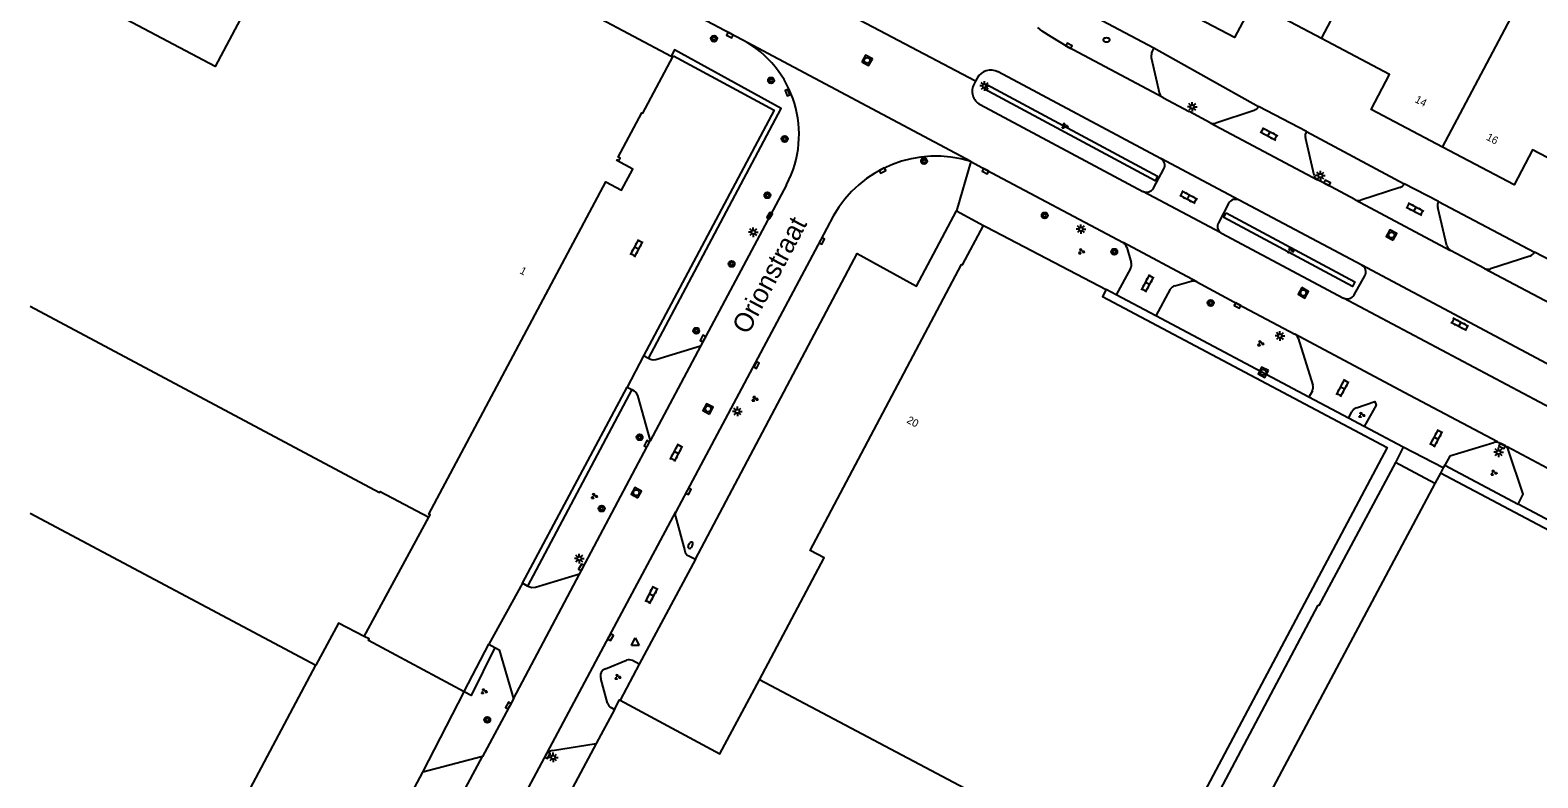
# Model space of a CAD drawing. Extents: x 135999 to 138000, y 396000 to 398501.
# Drawn here: x 136000 to 136196.7, y 398288.4 to 398385.9 of the extents above; entities that cross this region are included whole.
import ezdxf

# ---------------------------------------------------------------- set-up
doc = ezdxf.new("R2010")
doc.units = 0
for name, color, linetype in [('gg-afsc-hekwerk', 7, 'Continuous'), ('gg-anno-huisnummerreeks BGT', 7, 'Continuous'), ('gg-anno-openbare ruimte label', 7, 'Continuous'), ('gg-bbg-bijgebouw', 7, 'Continuous'), ('gg-bbg-hoofdgebouw', 7, 'Continuous'), ('gg-bbg-tussenscheiding', 7, 'Continuous'), ('gg-knt-verharding', 7, 'Continuous'), ('gg-knt-verharding nz', 7, 'Continuous'), ('gt-grn-groengrens', 7, 'Continuous'), ('gt-grn-vlakafsluiter', 7, 'Continuous'), ('gt-grn-weggrens', 7, 'Continuous'), ('gt-symb-boom', 7, 'Continuous'), ('gt-symb-brandkraan', 7, 'Continuous'), ('gt-symb-groenvak', 7, 'Continuous'), ('gt-symb-klinker verharding', 7, 'Continuous'), ('gt-symb-kolk', 7, 'Continuous'), ('gt-symb-lichtmast', 7, 'Continuous'), ('gt-symb-rioolschacht', 7, 'Continuous'), ('gt-symb-waterafsluiter', 7, 'Continuous')]:
    doc.layers.add(name, color=color, linetype=linetype)

# ---------------------------------------------------------------- blocks, each defined once
blk = doc.blocks.new('gt0-RS')
at = {"layer": 'gt-symb-rioolschacht'}
blk.add_lwpolyline([(-0.5, -0.5), (0.5, -0.5), (0.5, 0.5), (-0.5, 0.5)], close=True, dxfattribs=at)
blk.add_circle((0, 0), 0.375, dxfattribs=at)
blk = doc.blocks.new('gt0-BOOM')
at = {"layer": 'gt-symb-boom'}
for radius in [0.4, 0.2]:
    blk.add_circle((0, 0), radius, dxfattribs=at)
blk = doc.blocks.new('gt0-KOLK')
at = {"layer": 'gt-symb-kolk'}
blk.add_lwpolyline([(0, 0), (0.38, 0), (0.38, 0.4), (-0.38, 0.4), (-0.38, 0), (0, 0)], dxfattribs=at)
blk = doc.blocks.new('gt0-KL1')
at = {"layer": 'gt-symb-klinker verharding'}
for p, q in [((-1.15, 0.3), (1.15, 0.3)), ((-1, -0.3), (-1, 0.3)), ((-0.5, 0.3), (-0.5, 0.45)), ((0, -0.3), (0, 0.3)), ((0.5, 0.3), (0.5, 0.45)), ((1, -0.3), (1, 0.3)), ((-1.15, -0.3), (1.15, -0.3)), ((-0.5, -0.45), (-0.5, -0.3)), ((0.5, -0.45), (0.5, -0.3))]:
    blk.add_line(p, q, dxfattribs=at)
blk = doc.blocks.new('gt0-LMAST')
at = {"layer": 'gt-symb-lichtmast'}
for p, q in [((-0.18, 0.17), (-0.45, 0.44)), ((-0.01, 0.25), (-0.01, 0.62)), ((0.17, 0.17), (0.44, 0.44)), ((-0.26, 0), (-0.63, 0)), ((-0.18, -0.18), (-0.45, -0.45)), ((-0.01, -0.25), (-0.01, -0.63)), ((0.44, -0.45), (0.17, -0.18)), ((0.24, 0), (0.62, 0))]:
    blk.add_line(p, q, dxfattribs=at)
blk.add_circle((-0.01, 0), 0.25, dxfattribs=at)
blk = doc.blocks.new('gt0-BR')
at = {"layer": 'gt-symb-brandkraan'}
for centre, radius, start, end in [((-0.24, 0), 0.206, 107.5669, 252.4331), ((0.6, -2.66), 3, 106.892, 107.5669), ((0, -0.69), 0.938, 73.108, 106.892), ((-0.6, -2.66), 3, 72.4331, 73.108), ((0.24, 0), 0.206, 287.567, 72.4331), ((0.6, 2.66), 3, 252.4331, 253.108), ((0, 0.69), 0.938, 253.108, 286.8921), ((-0.6, 2.66), 3, 286.8921, 287.567)]:
    blk.add_arc(centre, radius, start, end, dxfattribs=at)
blk = doc.blocks.new('gt0-GRVAK')
at = {"layer": 'gt-symb-groenvak'}
for p, q in [((-0.11, 0.19), (-0.23, 0.24)), ((-0.18, 0.15), (0.09, 0.15)), ((-0.09, 0.21), (-0.16, 0.32)), ((-0.05, 0.21), (-0.05, 0.39)), ((0, 0.21), (0.06, 0.32)), ((0.02, 0.19), (0.13, 0.24)), ((0.26, -0.05), (0.2, 0.06)), ((0.3, -0.05), (0.3, 0.13)), ((0.35, -0.05), (0.41, 0.06)), ((-0.24, -0.23), (-0.36, -0.18)), ((-0.32, -0.26), (-0.05, -0.26)), ((-0.23, -0.21), (-0.29, -0.1)), ((-0.18, -0.2), (-0.18, -0.02)), ((-0.14, -0.21), (-0.07, -0.1)), ((-0.12, -0.23), (0, -0.18)), ((0.24, -0.07), (0.12, -0.02)), ((0.17, -0.11), (0.44, -0.11)), ((0.37, -0.07), (0.49, -0.02))]:
    blk.add_line(p, q, dxfattribs=at)
blk = doc.blocks.new('gt0-WAFSL')
at = {"layer": 'gt-symb-waterafsluiter'}
for p, q in [((-0.5, -0.33), (0, 0.67)), ((0, 0.67), (0.5, -0.33)), ((0.5, -0.33), (-0.5, -0.33))]:
    blk.add_line(p, q, dxfattribs=at)

msp = doc.modelspace()

# ---------------------------------------------------------------- linework, layer by layer
at = {"layer": 'gg-afsc-hekwerk'}
for p, q in [((136183.24, 398326.77), (136178.09, 398329.51)), ((136043.57, 398306.81), (136052.02, 398322.34)), ((136167.99, 398310.89), (136138.73, 398255.81)), ((136076.21, 398297.29), (136073.82, 398292.82)), ((136073.82, 398292.82), (136050.34, 398248.8))]:
    msp.add_line(p, q, dxfattribs=at)
for points in [[(136178.09, 398329.51), (136168.12, 398310.82), (136167.99, 398310.89)], [(136043.57, 398306.81), (136043.56, 398306.78), (136040.21, 398308.54), (136037.28, 398303.04)], [(136076.95, 398298.47), (136089.98, 398291.49), (136095.14, 398301.12)], [(136076.21, 398297.29), (136076.86, 398298.52), (136076.95, 398298.47)]]:
    msp.add_lwpolyline(points, dxfattribs=at)
at = {"layer": 'gg-bbg-bijgebouw'}
msp.add_line((136183.96, 398328.12), (136183.24, 398326.77), dxfattribs=at)
at = {"layer": 'gg-bbg-hoofdgebouw'}
for p, q in [((136037.76, 398406.86), (136083.62, 398382.52)), ((136083.62, 398382.52), (136083.85, 398382.4)), ((136124.36, 398360.42), (136124.79, 398360.19)), ((136124.79, 398360.19), (136140.35, 398352.08)), ((136183.24, 398326.77), (136143.95, 398252.99)), ((136216.25, 398310.99), (136183.96, 398328.12)), ((136000, 398322.88), (136037.28, 398303.04))]:
    msp.add_line(p, q, dxfattribs=at)
for points in [[(136019.2, 398399.67), (136030.72, 398393.55), (136024.13, 398381.14), (136012.54, 398387.29)], [(136168.43, 398384.8), (136159.52, 398389.49), (136157.12, 398384.93), (136147.8, 398389.85)], [(136184.25, 398370.64), (136174.93, 398375.55), (136177.33, 398380.1), (136168.43, 398384.8)], [(136052.02, 398322.34), (136052.2, 398322.66), (136051.99, 398322.77), (136075.09, 398366.13), (136077.15, 398365.03), (136078.62, 398367.78), (136076.54, 398368.9), (136076.58, 398368.98), (136076.8, 398368.86), (136076.97, 398369.19), (136076.71, 398369.33), (136079.81, 398375.13), (136079.93, 398375.07), (136083.85, 398382.4)], [(136204.89, 398365.61), (136195.97, 398370.28), (136193.57, 398365.72), (136184.25, 398370.64)], [(136095.14, 398301.12), (136103.58, 398317.07), (136101.77, 398318.03), (136121.5, 398355.33), (136121.6, 398355.27), (136124.36, 398360.42)], [(136140.35, 398352.08), (136139.88, 398351.17), (136177.02, 398331.46), (136146.5, 398273.94), (136095.14, 398301.12)], [(136000, 398349.9), (136045.57, 398325.58), (136045.65, 398325.72), (136052.02, 398322.34)], [(136000, 398233.59), (136000.25, 398233.46), (136011.09, 398253.85), (136000.68, 398259.36), (136013.45, 398283.38), (136023.88, 398277.84), (136037.28, 398303.04)]]:
    msp.add_lwpolyline(points, dxfattribs=at)
at = {"layer": 'gg-bbg-tussenscheiding'}
for p, q in [((136168.43, 398384.8), (136179.77, 398406.28)), ((136184.25, 398370.64), (136198.11, 398396.88))]:
    msp.add_line(p, q, dxfattribs=at)
at = {"layer": 'gg-knt-verharding'}
for p, q in [((136033.01, 398416.54), (136092.88, 398384.66)), ((136132.73, 398390.93), (136146.59, 398383.6)), ((136092.88, 398384.66), (136092.9, 398384.65)), ((136146.59, 398383.6), (136146.36, 398383.14)), ((136083.85, 398382.4), (136083.93, 398382.54)), ((136146.25, 398382.35), (136147.34, 398377.61)), ((136123.53, 398379.64), (136123.33, 398379.26)), ((136147.46, 398369.17), (136126.26, 398380.46)), ((136123.33, 398379.26), (136123.13, 398378.88)), ((136123.93, 398376.19), (136145.16, 398364.87)), ((136147.75, 398377.11), (136151.19, 398375.27)), ((136159.67, 398375.43), (136154.66, 398373.76)), ((136166.49, 398372.66), (136160.25, 398375.94)), ((136153.92, 398373.82), (136151.19, 398375.27)), ((136167.49, 398366.97), (136166.35, 398371.89)), ((136146.52, 398365.3), (136147.89, 398367.81)), ((136147.49, 398369.15), (136147.46, 398369.17)), ((136098.66, 398365.73), (136087.46, 398344.66)), ((136183.71, 398363.55), (136179.25, 398365.85)), ((136173.71, 398355.23), (136157.7, 398363.72)), ((136178.66, 398365.37), (136173.58, 398363.73)), ((136120.84, 398362.32), (136124.36, 398360.42)), ((136156.32, 398363.29), (136155, 398360.77)), ((136184.81, 398357.77), (136183.62, 398362.77)), ((136155.33, 398359.47), (136155.42, 398359.42)), ((136155.42, 398359.42), (136171.34, 398350.95)), ((136143.05, 398357.56), (136143.62, 398355.58)), ((136189.72, 398354.81), (136185.3, 398357.15)), ((136195.64, 398356.41), (136190.48, 398354.74)), ((136199.48, 398355.23), (136196.22, 398356.94)), ((136143.54, 398354.81), (136141.68, 398351.35)), ((136172.71, 398351.35), (136174.11, 398353.86)), ((136141.68, 398351.35), (136140.35, 398352.08)), ((136148.72, 398352.1), (136146.85, 398348.62)), ((136149.31, 398352.54), (136151.45, 398353.14)), ((136166.82, 398338), (136146.85, 398348.62)), ((136165.39, 398345.7), (136167.33, 398339.59)), ((136080.68, 398343.08), (136080.02, 398343.43)), ((136064.24, 398313.74), (136077.86, 398339.34)), ((136077.86, 398339.34), (136078.47, 398339.02)), ((136167.26, 398338.84), (136166.82, 398338)), ((136171.97, 398335.26), (136172.42, 398336.12)), ((136174.01, 398334.18), (136171.97, 398335.26)), ((136179.1, 398331.51), (136174.01, 398334.18)), ((136071.65, 398314.92), (136080.89, 398332.3)), ((136179.1, 398331.51), (136178.09, 398329.51)), ((136191.69, 398332.03), (136192.4, 398331.67)), ((136184.53, 398329.14), (136194.09, 398324.06)), ((136084.18, 398322.44), (136085.38, 398317.96)), ((136085.91, 398317.32), (136086.81, 398316.9)), ((136064.87, 398313.38), (136064.24, 398313.74)), ((136059.85, 398305.78), (136060.63, 398305.36)), ((136075.07, 398302.59), (136077.81, 398303.7)), ((136079.46, 398303.2), (136076.95, 398298.47)), ((136079.46, 398303.2), (136078.57, 398303.64)), ((136075.33, 398298.1), (136074.43, 398301.31)), ((136051.23, 398289.08), (136056.61, 398299.58)), ((136063.07, 398298.65), (136059.01, 398291.15)), ((136075.79, 398297.51), (136076.21, 398297.29)), ((136068.14, 398291.91), (136073.82, 398292.82)), ((136047.54, 398254.3), (136067.44, 398291.63)), ((136059.01, 398291.15), (136051.23, 398289.08))]:
    msp.add_line(p, q, dxfattribs=at)
for points in [[(136083.93, 398382.54), (136097.07, 398375.46), (136080.02, 398343.43)], [(136122.7, 398368.75), (136124.71, 398367.69), (136142.57, 398358.18)], [(136172.81, 398363.79), (136169.08, 398365.8), (136167.93, 398366.38)], [(136104.76, 398361.65), (136103.09, 398358.49), (136085.71, 398325.84), (136084.21, 398323.07)], [(136086.81, 398316.9), (136107.86, 398356.74), (136115.63, 398352.49), (136120.84, 398362.32)], [(136152.21, 398353.05), (136157.6, 398350.16), (136164.99, 398346.25)], [(136087.46, 398344.66), (136081.62, 398342.88), (136081.26, 398342.84), (136080.92, 398342.95), (136080.68, 398343.08)], [(136078.47, 398339.02), (136078.71, 398338.89), (136079.03, 398338.62), (136079.23, 398338.25), (136080.89, 398332.3)], [(136173, 398336.62), (136175.43, 398337.43), (136175.59, 398336.96), (136174.01, 398334.18)], [(136190.92, 398332.07), (136185.19, 398330.32), (136184.53, 398329.14)], [(136194.09, 398324.06), (136194.74, 398325.37), (136192.81, 398331.17)], [(136071.65, 398314.92), (136065.9, 398313.19), (136065.45, 398313.15), (136065.03, 398313.29), (136064.87, 398313.38)], [(136056.61, 398299.58), (136044.12, 398306.25), (136044.22, 398306.47), (136043.57, 398306.81)], [(136056.61, 398299.58), (136056.63, 398299.61), (136059.85, 398305.78)], [(136060.63, 398305.36), (136061.16, 398305.07), (136063.07, 398298.65)]]:
    msp.add_lwpolyline(points, dxfattribs=at)
for centre, radius, start, end in [((136086.3, 398372.3), 14, 332.0081, 61.8671), ((136147.93, 398382.52), 1.69, 158.5836, 185.8472), ((136125.31, 398378.65), 2.04, 62.5683, 150.9921), ((136124.85, 398377.93), 1.97, 151.0625, 241.968), ((136148.24, 398377.94), 0.954, 199.9479, 239.3208), ((136159.26, 398376.48), 1.12, 291.397, 331.6982), ((136154.36, 398374.7), 0.984, 243.4164, 287.5962), ((136167.28, 398372.12), 0.959, 145.6989, 193.5861), ((136118.1, 398354.14), 15.31, 72.5297, 150.6241), ((136147.01, 398368.28), 0.996, 331.8789, 61.025), ((136168.42, 398367.2), 0.955, 194.3859, 239.5414), ((136178.44, 398366.25), 0.908, 284.2709, 333.498), ((136145.62, 398365.8), 1.04, 243.5916, 330.8255), ((136157.22, 398362.81), 1.02, 62.1697, 151.9831), ((136173.26, 398364.67), 0.989, 242.8416, 288.487), ((136184.7, 398363.04), 1.11, 152.9096, 193.9882), ((136155.82, 398360.29), 0.953, 149.5102, 238.832), ((136141.98, 398357.23), 1.12, 17.3272, 58.3715), ((136185.83, 398358.08), 1.07, 196.6864, 240.0438), ((136195.35, 398357.31), 0.943, 287.5157, 337.1583), ((136142.64, 398355.29), 1.02, 331.8614, 16.183), ((136173.23, 398354.35), 1.01, 330.6597, 61.4509), ((136190.22, 398355.99), 1.28, 246.9429, 281.6805), ((136149.45, 398351.73), 0.817, 99.6032, 153.4868), ((136151.7, 398351.93), 1.24, 65.5204, 101.3674), ((136171.82, 398351.85), 1.02, 242.1314, 330.389), ((136164.51, 398345.48), 0.914, 14.3957, 58.373), ((136166.4, 398339.3), 0.967, 332.0521, 17.6974), ((136173.25, 398335.74), 0.912, 105.9609, 155.6796), ((136191.25, 398331.13), 1.01, 64.1447, 109.4956), ((136191.84, 398330.81), 1.03, 20.3269, 56.8542), ((136085.07, 398322.7), 0.934, 156.7313, 195.9565), ((136086.25, 398318.13), 0.883, 191.1708, 247.0573), ((136078.13, 398302.84), 0.918, 61.3164, 110.2331), ((136075.41, 398301.62), 1.03, 109.4364, 197.5408), ((136076.18, 398298.29), 0.871, 192.4937, 243.6839), ((136068.57, 398289.82), 2.13, 101.7617, 122.1231)]:
    msp.add_arc(centre, radius, start, end, dxfattribs=at)
at = {"layer": 'gg-knt-verharding nz'}
for p, q in [((136153.92, 398373.82), (136167.93, 398366.38)), ((136157.7, 398363.72), (136147.49, 398369.15)), ((136155.33, 398359.47), (136145.16, 398364.87)), ((136172.81, 398363.79), (136185.3, 398357.15)), ((136152.21, 398353.05), (136142.57, 398358.18)), ((136216.61, 398332.4), (136173.71, 398355.23)), ((136214.28, 398328.11), (136171.34, 398350.95)), ((136179.22, 398338.61), (136164.99, 398346.25)), ((136087.46, 398344.66), (136080.89, 398332.3)), ((136191.42, 398332.21), (136179.22, 398338.61)), ((136191.69, 398332.03), (136191.42, 398332.21)), ((136192.4, 398331.67), (136192.66, 398331.52)), ((136209.7, 398322.45), (136192.66, 398331.52)), ((136184.34, 398328.8), (136183.96, 398328.12)), ((136184.53, 398329.14), (136184.34, 398328.8)), ((136063.07, 398298.65), (136071.65, 398314.92))]:
    msp.add_line(p, q, dxfattribs=at)
for points in [[(136147.75, 398377.11), (136135.42, 398383.68), (136133.18, 398385.03), (136132.03, 398385.77), (136131.43, 398386.24)], [(136189.72, 398354.81), (136199.92, 398349.42), (136205.16, 398346.63)], [(136067.44, 398291.63), (136075.55, 398306.79), (136084.21, 398323.07)], [(136027.11, 398231.15), (136033.64, 398243.56), (136043.32, 398261.71), (136052.94, 398279.78), (136059.01, 398291.15)]]:
    msp.add_lwpolyline(points, dxfattribs=at)
at = {"layer": 'gt-grn-groengrens'}
for p, q in [((136122.7, 398368.75), (136120.84, 398362.32)), ((136078.47, 398339.02), (136064.87, 398313.38))]:
    msp.add_line(p, q, dxfattribs=at)
for points in [[(136080.68, 398343.08), (136097.98, 398375.67), (136084.05, 398383.32), (136083.62, 398382.52)], [(136124.78, 398378.79), (136147.08, 398366.84), (136146.77, 398366.26), (136124.47, 398378.21), (136124.78, 398378.79)], [(136156.02, 398362.05), (136172.81, 398353.05), (136172.5, 398352.47), (136155.71, 398361.47), (136156.02, 398362.05)], [(136060.63, 398305.36), (136057.51, 398299.1), (136056.61, 398299.58)]]:
    msp.add_lwpolyline(points, dxfattribs=at)
at = {"layer": 'gt-grn-vlakafsluiter'}
for p, q in [((136146.59, 398383.6), (136160.25, 398375.94)), ((136166.49, 398372.66), (136179.25, 398365.85)), ((136183.71, 398363.55), (136196.22, 398356.94)), ((136146.85, 398348.62), (136141.68, 398351.35)), ((136080.02, 398343.43), (136077.86, 398339.34)), ((136171.97, 398335.26), (136166.82, 398338)), ((136202.65, 398319.49), (136194.09, 398324.06)), ((136086.81, 398316.9), (136079.46, 398303.2)), ((136064.24, 398313.74), (136059.85, 398305.78)), ((136024.5, 398239.03), (136051.23, 398289.08))]:
    msp.add_line(p, q, dxfattribs=at)
at = {"layer": 'gt-grn-weggrens'}
for p, q in [((136123.33, 398379.26), (136103.25, 398389.8)), ((136122.7, 398368.75), (136092.9, 398384.65)), ((136184.34, 398328.8), (136179.1, 398331.51))]:
    msp.add_line(p, q, dxfattribs=at)

# ---------------------------------------------------------------- block references
at = {"layer": 'gt-symb-boom'}
for p in [(136089.21, 398384.79), (136096.65, 398379.34), (136098.43, 398371.7), (136116.61, 398368.81), (136096.18, 398364.36), (136132.35, 398361.72), (136091.5, 398355.41), (136141.41, 398356.98), (136154, 398350.31), (136086.88, 398346.68), (136079.49, 398332.79), (136074.56, 398323.49), (136059.62, 398295.92)]:
    msp.add_blockref('gt0-BOOM', p, dxfattribs=at)
at = {"layer": 'gt-symb-brandkraan'}
msp.add_blockref('gt0-BR', (136140.41, 398384.63), dxfattribs=at)
at = {"layer": 'gt-symb-brandkraan', "rotation": -118.74303563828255}
msp.add_blockref('gt0-BR', (136086.13, 398318.69), dxfattribs=at)
at = {"layer": 'gt-symb-groenvak'}
for p in [(136134.94, 398373.4), (136137.1, 398357.04), (136164.39, 398357.13), (136160.48, 398345.03), (136094.52, 398337.8), (136173.66, 398335.69), (136190.9, 398328.16), (136073.56, 398325.11), (136076.62, 398301.51), (136059.19, 398299.64)]:
    msp.add_blockref('gt0-GRVAK', p, dxfattribs=at)
at = {"layer": 'gt-symb-klinker verharding'}
for p, rotation in [((136161.61, 398372.37), -27.89727103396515), ((136151.11, 398364.11), -27.974729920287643), ((136180.65, 398362.55), -27.897271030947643), ((136079.11, 398357.45), 61.974683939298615), ((136145.76, 398352.85), 61.81960518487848), ((136186.48, 398347.51), 152.28149837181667), ((136171.21, 398339.2), 61.81960518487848), ((136183.42, 398332.65), 61.81960518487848), ((136084.31, 398330.77), 62.02527007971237), ((136081.06, 398312.21), 62.025270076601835)]:
    msp.add_blockref('gt0-KL1', p, dxfattribs=dict(at, rotation=rotation))
at = {"layer": 'gt-symb-kolk'}
for p, rotation in [((136091.37, 398385.44), 152.28149837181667), ((136135.42, 398383.68), -28.37344876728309), ((136098.6, 398377.68), -69.57138285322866), ((136111.08, 398367.75), -152.69221992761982), ((136124.71, 398367.69), 152.23078730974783), ((136169.08, 398365.8), -28.308520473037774), ((136096.64, 398361.6), 61.71863891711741), ((136103.09, 398358.49), -117.89727103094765), ((136157.6, 398350.16), 151.76909817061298), ((136087.94, 398345.56), 61.89717643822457), ((136094.92, 398342.11), 61.89717643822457), ((136080.63, 398331.82), 61.89717643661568), ((136192.1, 398331.83), 153.20443508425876), ((136085.71, 398325.84), -118.02531606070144), ((136072.08, 398315.72), 61.89717644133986), ((136075.55, 398306.79), -118.14606961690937), ((136062.55, 398297.69), 61.47133250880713), ((136067.31, 398291.39), -117.79574833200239)]:
    msp.add_blockref('gt0-KOLK', p, dxfattribs=dict(at, rotation=rotation))
at = {"layer": 'gt-symb-lichtmast'}
for p in [(136124.52, 398378.62), (136151.6, 398375.9), (136168.31, 398366.92), (136094.34, 398359.54), (136137.08, 398359.94), (136163.04, 398346), (136092.26, 398336.16), (136191.56, 398330.83), (136071.64, 398316.96), (136068.24, 398291.02)]:
    msp.add_blockref('gt0-LMAST', p, dxfattribs=at)
at = {"layer": 'gt-symb-rioolschacht'}
for p, rotation in [((136109.18, 398381.96), -29.332790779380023), ((136177.58, 398359.17), 61.30721229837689), ((136166.08, 398351.63), -119.79461720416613), ((136160.85, 398341.27), 152.486938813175), ((136088.43, 398336.49), 62.02527007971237), ((136079.07, 398325.55), 60.255118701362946)]:
    msp.add_blockref('gt0-RS', p, dxfattribs=dict(at, rotation=rotation))
at = {"layer": 'gt-symb-waterafsluiter'}
msp.add_blockref('gt0-WAFSL', (136078.93, 398305.97), dxfattribs=at)

# ---------------------------------------------------------------- texts
at = {"layer": 'gg-anno-huisnummerreeks BGT'}
for s, rotation, p in [('14', 332.2, (136180.54, 398376.55)), ('16', 332.2, (136189.86, 398371.64)), ('1', 332, (136063.77, 398354.22)), ('20', 332.1, (136114.25, 398334.73))]:
    msp.add_text(s, height=1, rotation=rotation, dxfattribs=at).set_placement(p)
at = {"layer": 'gg-anno-openbare ruimte label'}
msp.add_text('Orionstraat', height=2.5, rotation=62, dxfattribs=at).set_placement((136093.65, 398346.07))

doc.saveas('drawing.dxf')
